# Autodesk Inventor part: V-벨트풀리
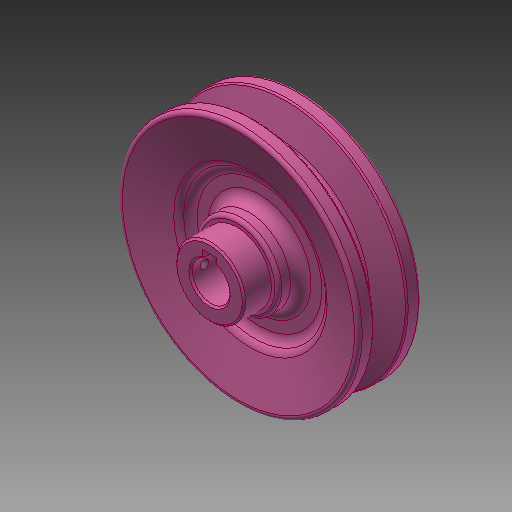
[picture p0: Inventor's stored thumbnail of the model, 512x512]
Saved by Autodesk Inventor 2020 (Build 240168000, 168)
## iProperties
Created: 2016-08
Part Number: V-벨트풀리
Material: 알루미늄 6061
Document SubType Name: Modeling
Designer: mduedu
Density: 2.71 g/cm^3
Appearance: 분홍색
Author: mduedu
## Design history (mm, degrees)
sketch "스케치1"
  geometry: L1 (0, 17.5)-(0, -9.5); L2 (10, 9.5)-(35, 9.5); L3 (35, 9.5)-(35, 4.825); L4 (35, 4.825)-(26, 2.074); L5 (26, 2.074)-(26, 0); L6 (0, 0)-(26, 0); L7 (0, -9.5)-(35, -9.5); L8 (35, -9.5)-(35, -4.825); L9 (35, -4.825)-(26, -2.074); L10 (26, -2.074)-(26, 0); L11 (32.3, 9.5)-(32.3, -9.5); L12 (10, 9.5)-(10, 17.5); L13 (10, 17.5)-(0, 17.5); 3 further points
  constraints: 26 end point, 7 point on line, 5 perpendicular, 3 symmetric about line, 2 parallel, 1 coincident, 1 horizontal alignment, 1 vertical
  dimensions: "d2" = 70 diameter of L8 L1; "d4" = 6.3 distance between parallel lines of L10 L11; "d5" = 2.7 distance between parallel lines of L11 L8; "d6" = 8 distance of point (32.3, -4) point (32.3, 4); "d7" = 34 deg angle of L9 L4; "d30" = 9.5 distance between parallel lines of L7 L6; "d32" = 27 distance between parallel lines of L13 L7; "d33" = 20 diameter of L12 L1
revolve "회전1" sketch "스케치1" stored, may be unused: angle "d8" = 90 deg
sketch "스케치2"
  geometry: L1 (-2, 0)-(2, 0); L2 (2, 0)-(2, 7.3); L3 (2, 7.3)-(-2, 7.3); L4 (-2, 7.3)-(-2, 0); C1 r 5.5 at (0, 0); 2 further points
  constraints: 8 end point, 2 coincident, 2 parallel, 1 centre point, 1 horizontal, 1 midpoint, 1 perpendicular
  dimensions: "d9" = 11 diameter of C1; "d11" = 4 distance of L2.end L3.end; "d34" = 12.8 dimension on C1 L3
extrude "돌출1" cut sketch "스케치2" extent not by distance; stored distance "d13" = 10; taper "d14" = 0 deg
sketch "스케치3"
  geometry: L1 (35, 4.825)-(26, 2.074) reference; L2 (26, 2.074)-(26, -2.074) reference; L3 (0, 0)-(26, 0); L4 (35, 9.5)-(35, 4.825) reference; L5 (-35, 9.5)-(35, 9.5) reference; L6 (35, 9.5)-(21, 5.22); L7 (21, 5.22)-(21, 3); L8 (21, 3)-(12, 3); L9 (12, 3)-(12, 9.5); L10 (0, 9.5)-(0, -9.5); L11 (5.123, -9.5)-(-5.5, -9.5) reference; L12 (12, 9.5)-(35, 9.5)
  constraints: 14 end point, 3 midpoint, 2 parallel, 2 perpendicular, 2 point on line, 1 collinear, 1 horizontal
  dimensions: "d15" = 3 distance between parallel lines of L3 L8; "d17" = 42 diameter of L7 L10; "d18" = 24 diameter of L9 L10
revolve "회전2" sketch "스케치3" stored, may be unused: angle "d19" = 90 deg
fillet "모깎기1" dims "d20" = 0.5, "d21" = 1, "d22" = 1
fillet "모깎기2" dims "d23" = 3
fillet "모깎기3" dims "d24" = 3
fillet "모깎기4" dims "d25" = 3
chamfer "모따기1" distance "d26" = 0.5; stored, may be unused: second distance "d27" = 2, angle "d28" = 45 deg
fillet "모깎기5" dims "d29" = 1
node "작업 평면1"
sketch "스케치4"
  geometry: L1 (-9.5, 17.5)-(9.5, 17.5) reference; 2 further points
  constraints: 1 vertical alignment
  dimensions: "d41" = 4 distance from line of L1 point (0, 13.5)
hole "구멍1" sketch "스케치4" at (0, 13.5) diameter "d42" = 2.459; stored, may be unused: countersink angle "d46" = 90 deg, drill point angle "d48" = 118 deg; dims "d43" = 6, "d44" = 4, "d45" = 2, "d47" = 8
node "솔리드1"
mirror "대칭1"
